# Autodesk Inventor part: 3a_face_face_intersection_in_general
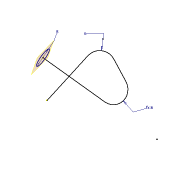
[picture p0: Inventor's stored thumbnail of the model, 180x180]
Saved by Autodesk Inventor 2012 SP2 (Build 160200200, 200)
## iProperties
Company: Autodesk, Inc.
Created: 2013-06
Part Number: 3a_face_face_intersection_in_general
Material: Default
Document SubType Name: Modeling
Designer: Glenn Chun
Density: 1 g/cm^3
Author: Glenn Chun
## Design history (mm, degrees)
sketch "Path1" dims "d0" = 6, "d1" = 6 (= d0)
node "Normal to Path1"
sketch "Profile1"
  geometry: C1 r 4 at (0, 0); 1 further point
  constraints: 1 centre point, 1 coincident
  dimensions: "d2" = 8 diameter of C1
